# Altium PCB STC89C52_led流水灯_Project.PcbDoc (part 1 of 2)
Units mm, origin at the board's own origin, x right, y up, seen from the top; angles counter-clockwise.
Board outline 100 x 80 mm, 2 copper layers (Top Layer, Bottom Layer); 175 components, 183 nets, 540 pads, 112 vias.
Unrouted connection lines stored in the file: 28.
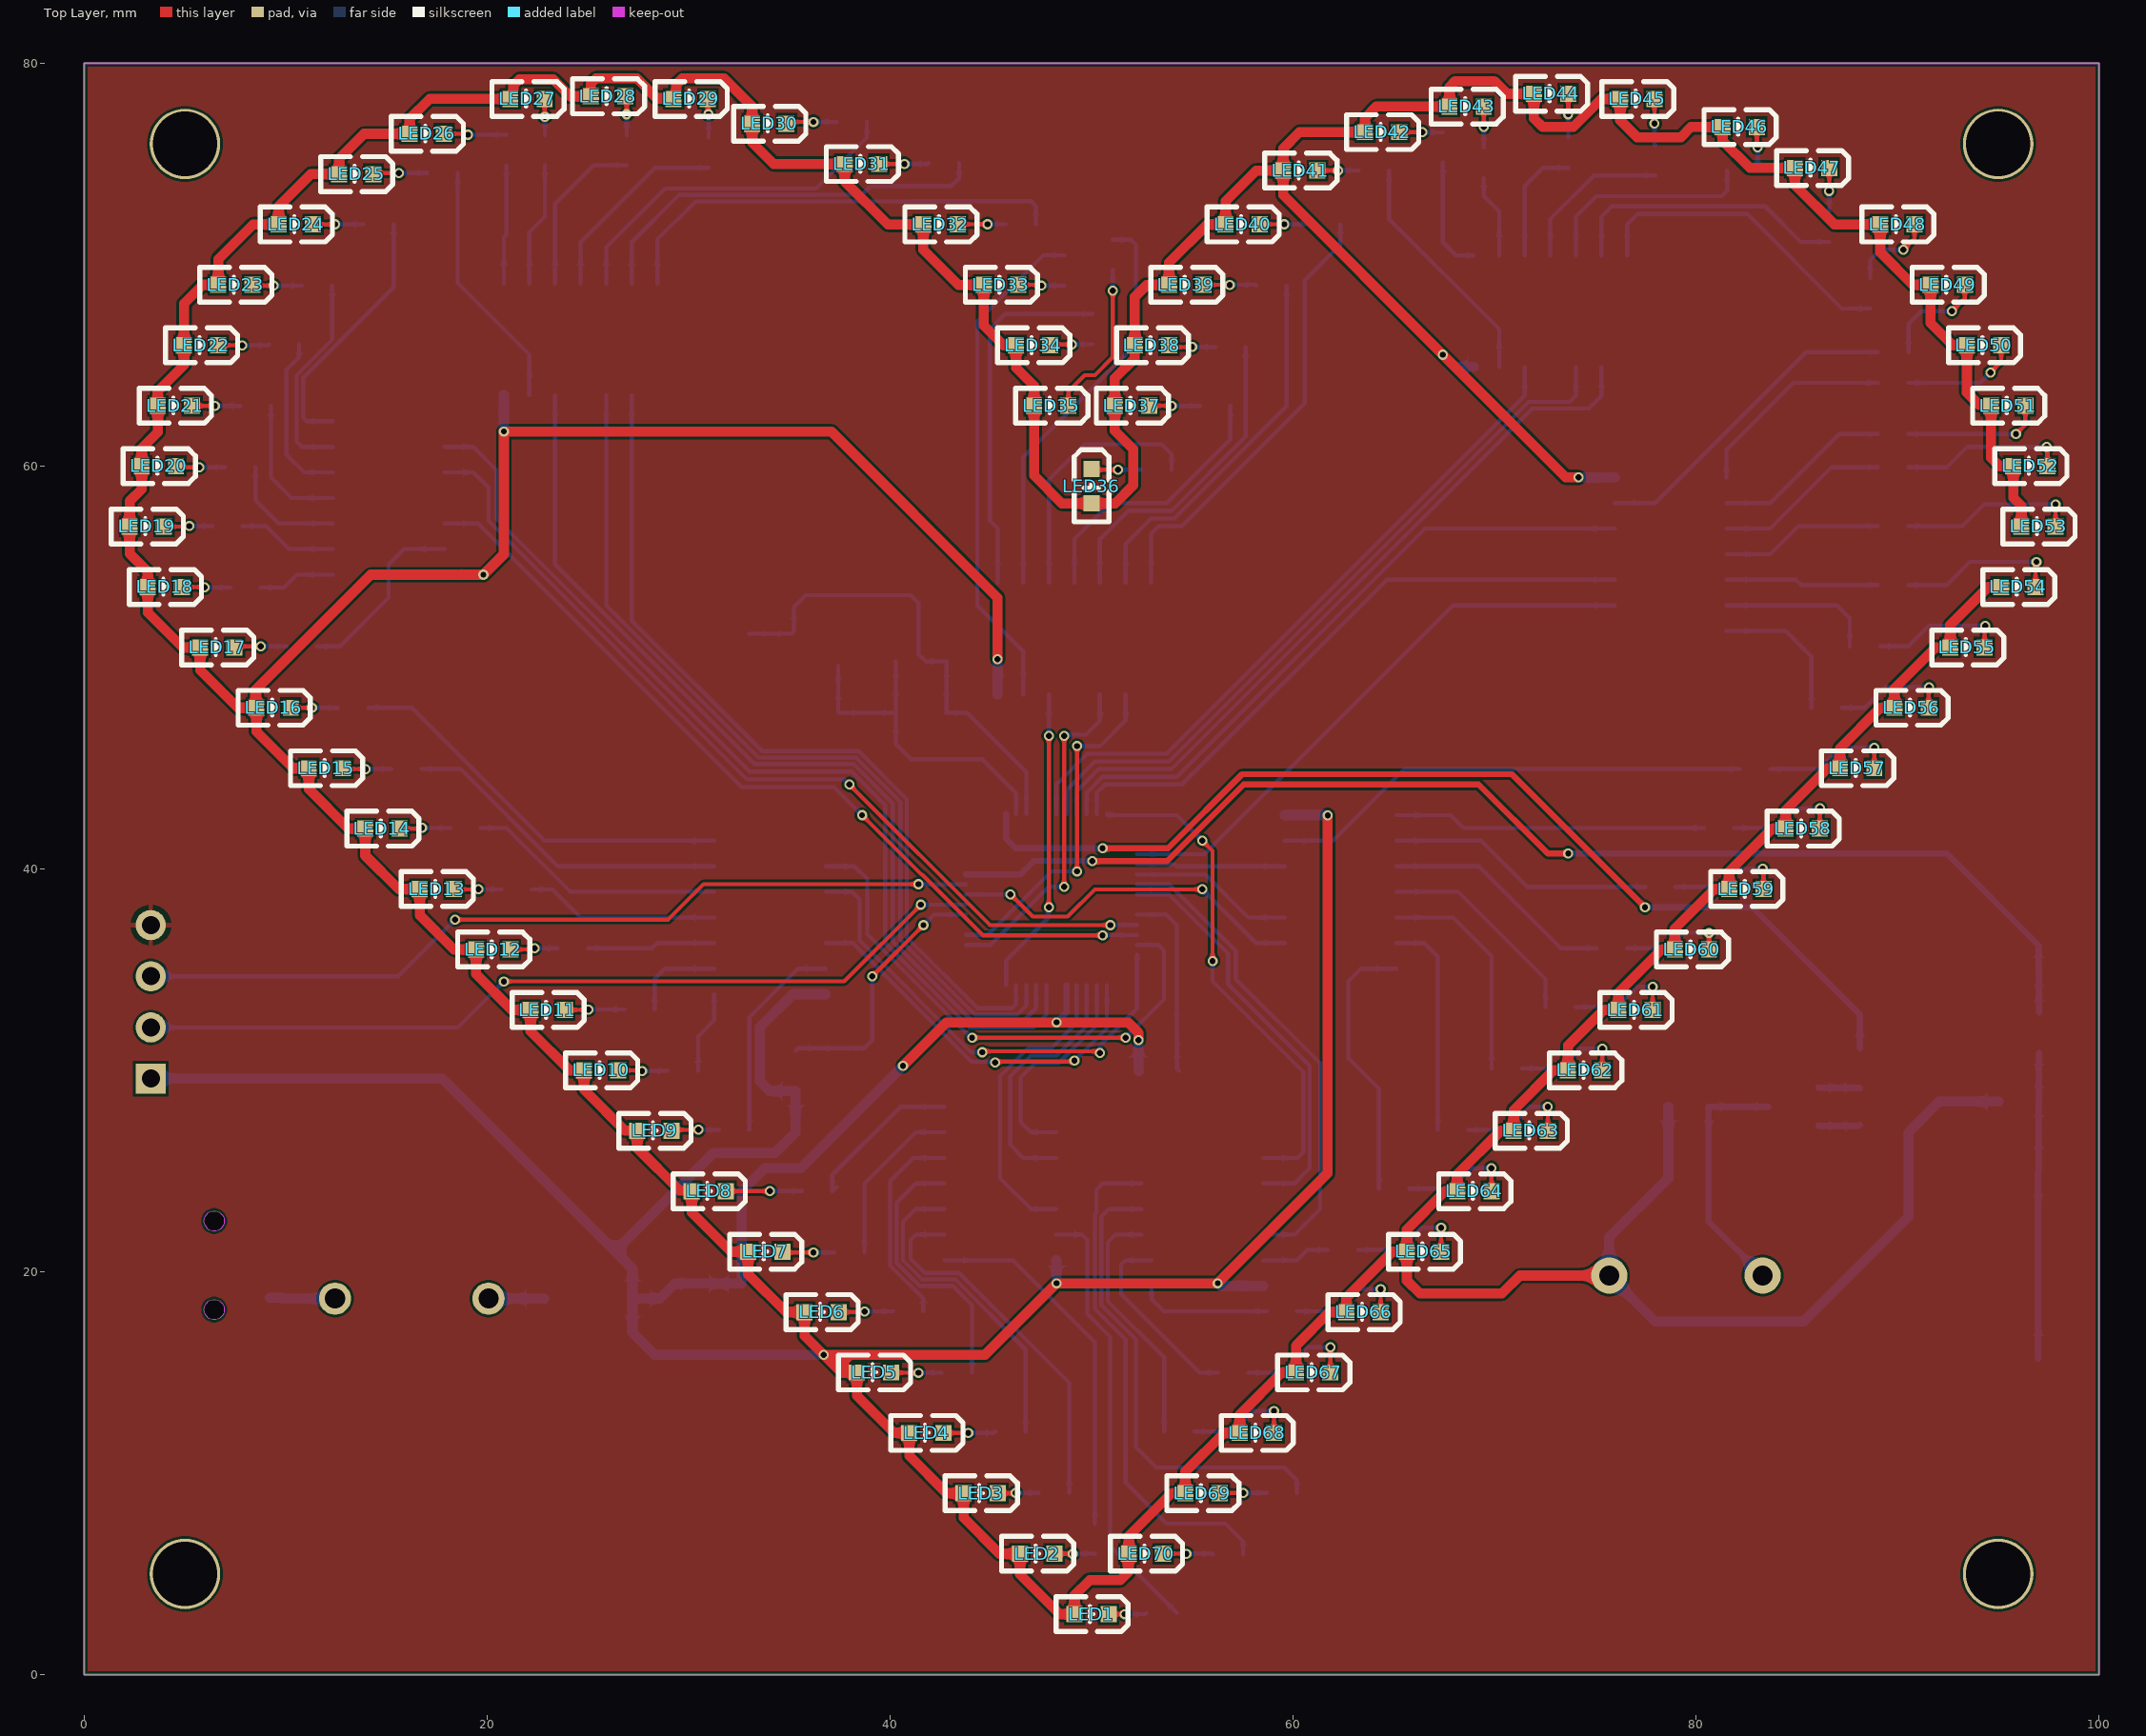
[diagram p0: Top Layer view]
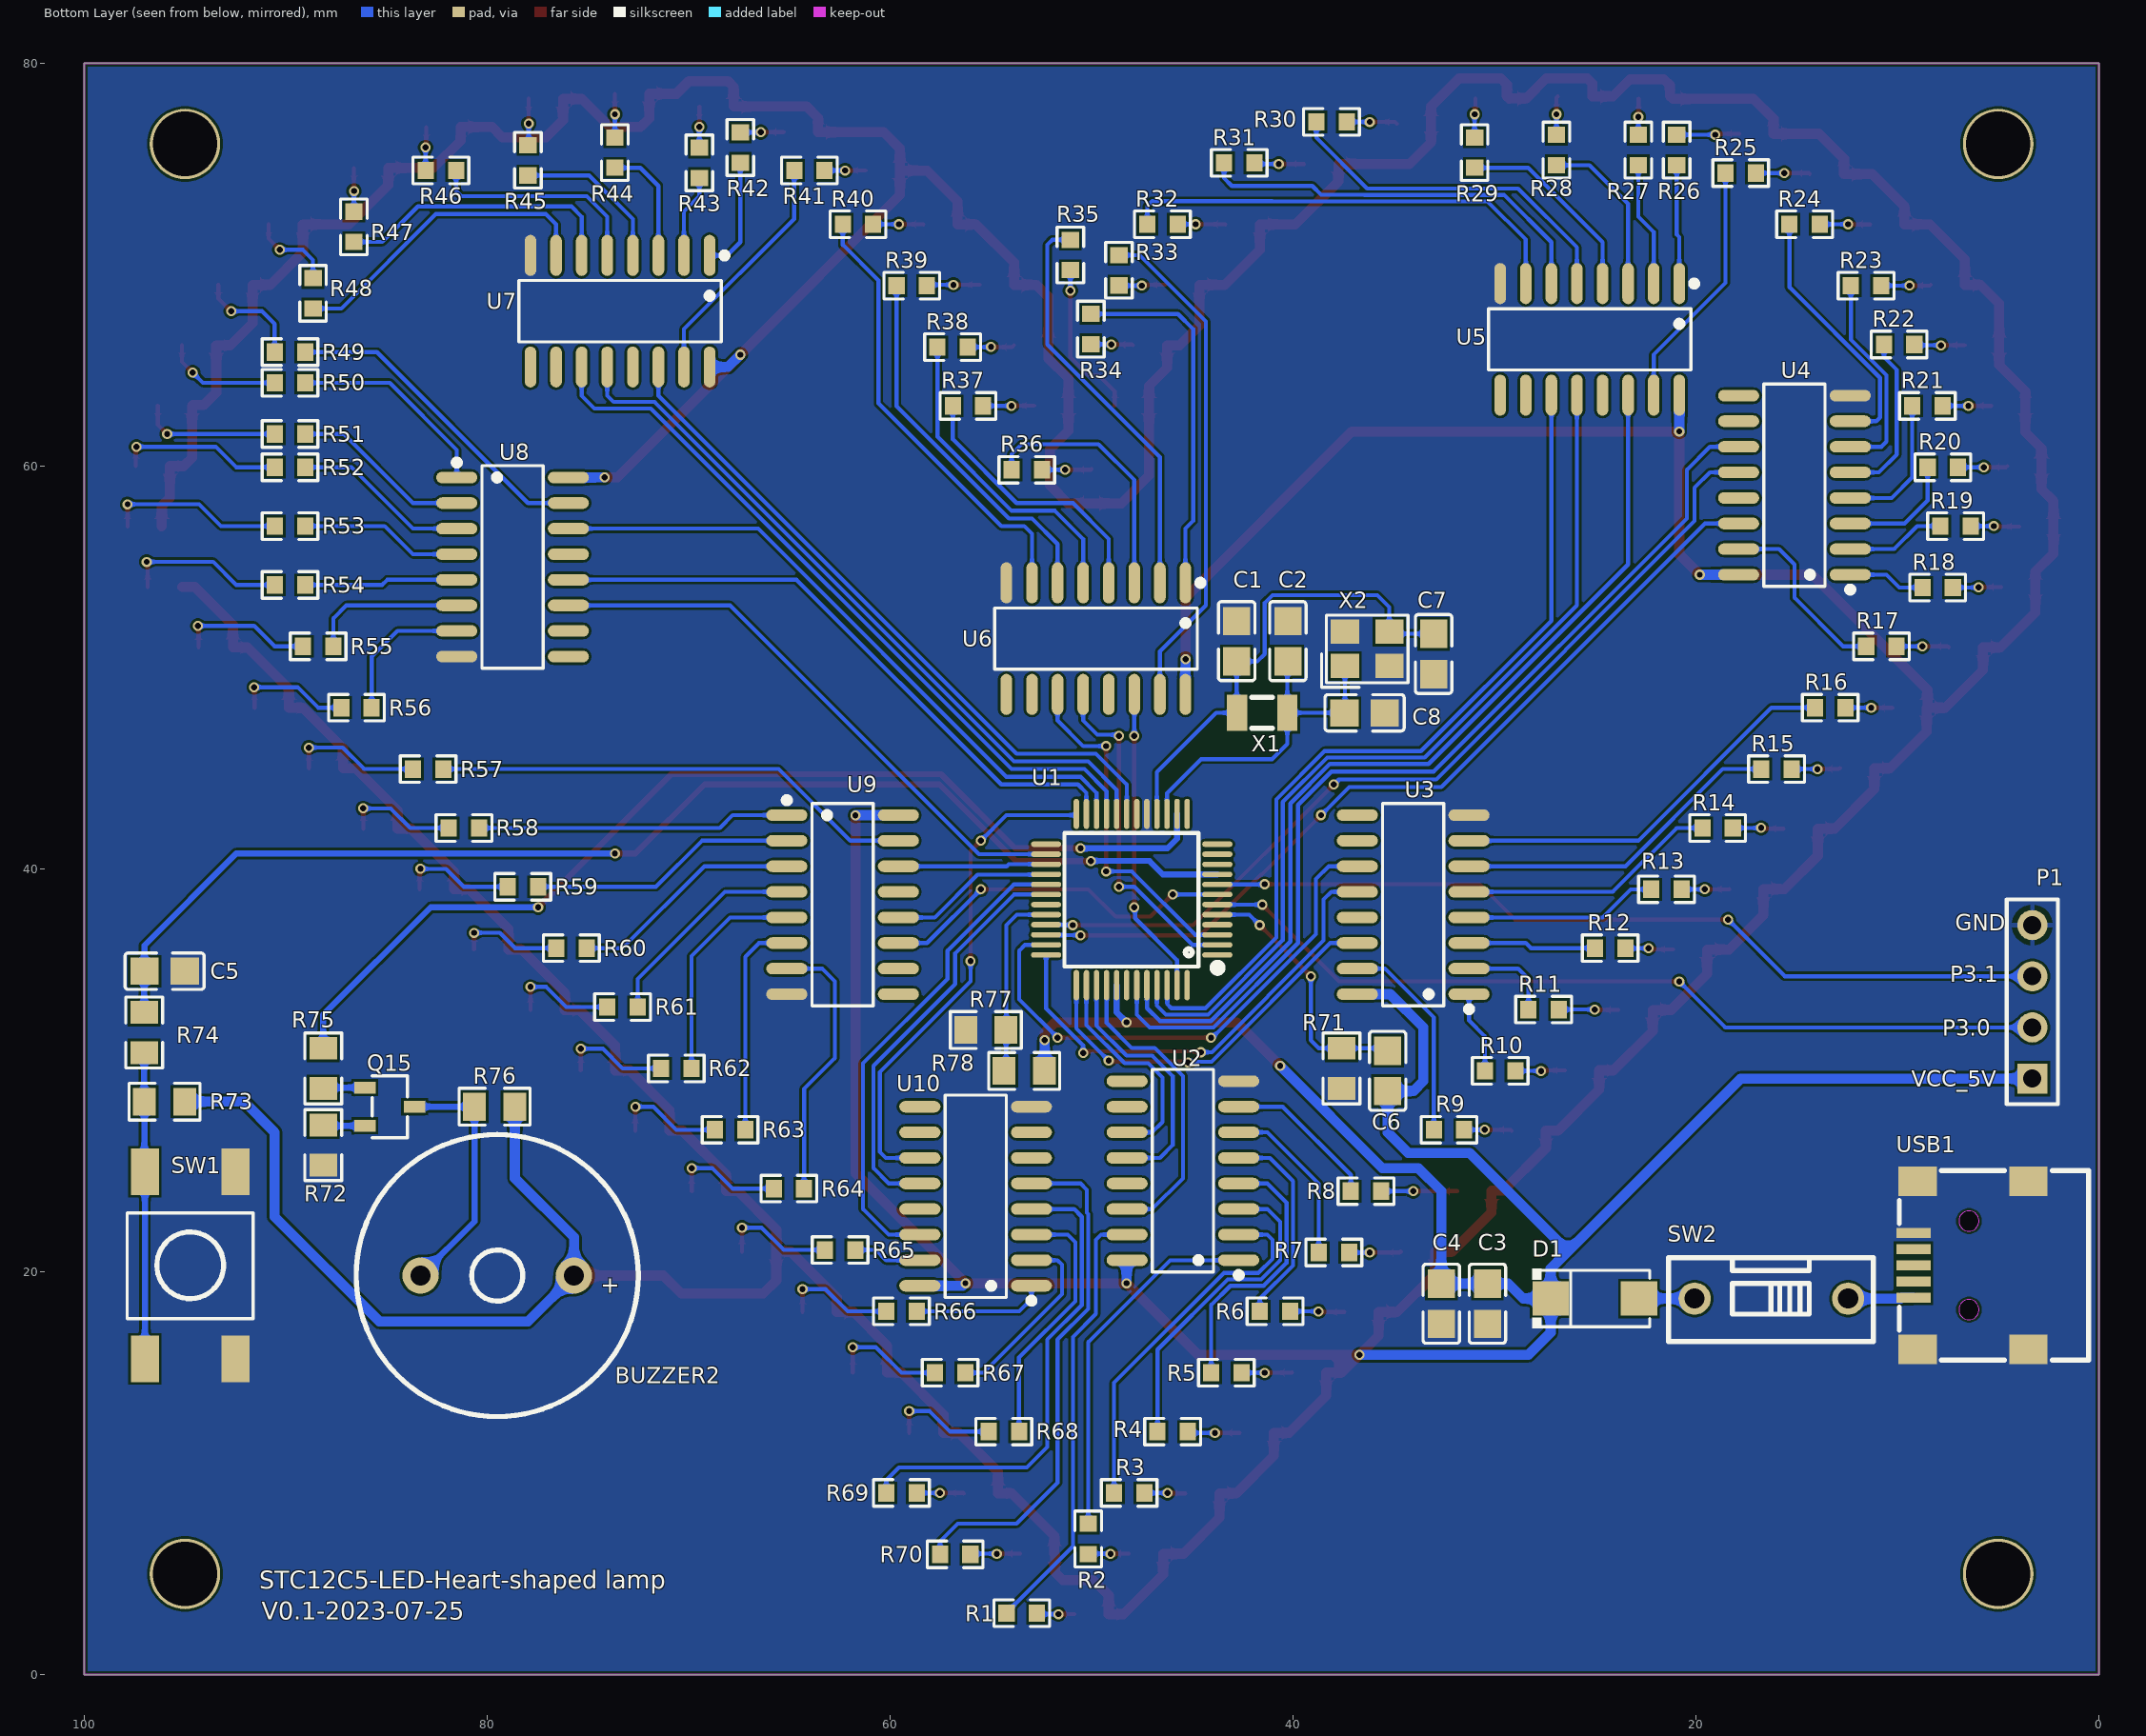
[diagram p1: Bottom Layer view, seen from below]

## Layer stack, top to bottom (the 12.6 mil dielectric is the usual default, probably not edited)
Top Solder: solder mask 0.0102, Solder Resist, Dk 3.5
Top Layer: signal copper 0.0356
Dielectric 1: dielectric 0.32, FR-4, Dk 4.8
Bottom Layer: signal copper 0.0356
Bottom Solder: solder mask 0.0102, Solder Resist, Dk 3.5

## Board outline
0,0 100,0 100,80 0,80

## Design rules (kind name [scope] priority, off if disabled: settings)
Clearance [All] p1: gap=0.12 ignorepadtopadclearanceinfootprint=FALSE
PolygonConnect [All] p1: thpad.connectstyle=Relief thpad.reliefconductorwidth=0.254 thpad.reliefentries=4 thpad.polygonreliefangle="90 Angle" thpad.airgapwidth=0.254 smdpad.connectstyle=Direct smdpad.reliefconductorwidth=0.254 smdpad.reliefentries=4 smdpad.polygonreliefangle="90 Angle" smdpad.airgapwidth=0.254 via.connectstyle=Direct via.reliefconductorwidth=0.254 via.reliefentries=4 via.polygonreliefangle="90 Angle" via.airgapwidth=0.254
RoutingVias [All] p1: holewidth=0.711 width=1.27 viastyle="Through Hole" minholewidth=0.3 minwidth=0.5 maxholewidth=0.711 maxwidth=1.27
SolderMaskExpansion [All] p1: expansion=0.102 istentingtop=FALSE
Width [All] p1: maxlimit=0.8 minlimit=0.16 preferedwidth=0.2
30 further rules are at their usual default settings.

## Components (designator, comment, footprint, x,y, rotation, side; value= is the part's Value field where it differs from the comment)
BUZZER2 "SFN-14045PA7.6" 插件,D=14mm 79.502,19.812 r0 bottom value=4000Hz
C1 "" C0805 42.799,51.308 r90 bottom value=22pF
C2 "" C0805 40.259,51.308 r90 bottom value=22pF
C3 "47uF" C0805 30.353,18.415 r90 bottom value=100uF
C4 "0.1uF" C0805 32.639,18.415 r90 bottom value=100uF
C5 "" C0805 96.012,34.925 r0 bottom value=0.1uF
C6 "" C0805 35.306,29.972 r270 bottom value=10uF
C7 "" C0805 33.02,50.673 r270 bottom value=22pF
C8 "" C0805 36.449,47.752 r180 bottom value=22pF
D1 "1N5819" SMA_L4.4-W2.6-LS5.0-RD 25.019,18.669 r180 bottom
LED1 "TLMG1100-GS08" LED0603 50,3 r180 top locked
LED2 "TLMG1100-GS08" LED0603 47.3,6 r180 top
LED3 "TLMG1100-GS08" LED0603 44.5,9 r180 top
LED4 "TLMG1100-GS08" LED0603 41.8,12 r180 top
LED5 "TLMG1100-GS08" LED0603 39.2,15 r180 top
LED6 "TLMG1100-GS08" LED0603 36.6,18 r180 top
LED7 "TLMG1100-GS08" LED0603 33.8,21 r180 top
LED8 "TLMG1100-GS08" LED0603 31,24 r180 top
LED9 "TLMG1100-GS08" LED0603 28.3,27 r180 top
LED10 "TLMG1100-GS08" LED0603 25.654,30 r180 top
LED11 "TLMG1100-GS08" LED0603 23,33 r180 top
LED12 "TLMG1100-GS08" LED0603 20.3,36 r180 top
LED13 "TLMG1100-GS08" LED0603 17.5,39 r180 top
LED14 "TLMG1100-GS08" LED0603 14.8,42 r180 top
LED15 "TLMG1100-GS08" LED0603 12,45 r180 top
LED16 "TLMG1100-GS08" LED0603 9.4,48 r180 top
LED17 "TLMG1100-GS08" LED0603 6.6,51 r180 top
LED18 "TLMG1100-GS08" LED0603 4,54 r180 top
LED19 "TLMG1100-GS08" LED0603 3.1,57 r180 top
LED20 "TLMG1100-GS08" LED0603 3.7,60 r180 top
LED21 "TLMG1100-GS08" LED0603 4.5,63 r180 top
LED22 "TLMG1100-GS08" LED0603 5.8,66 r180 top
LED23 "TLMG1100-GS08" LED0603 7.5,69 r180 top
LED24 "TLMG1100-GS08" LED0603 10.5,72 r180 top
LED25 "TLMG1100-GS08" LED0603 13.5,74.5 r180 top
LED26 "TLMG1100-GS08" LED0603 17,76.5 r180 top
LED27 "TLMG1100-GS08" LED0603 22,78.232 r180 top
LED28 "TLMG1100-GS08" LED0603 26,78.359 r180 top
LED29 "TLMG1100-GS08" LED0603 30.099,78.232 r180 top
LED30 "TLMG1100-GS08" LED0603 34,77 r180 top
LED31 "TLMG1100-GS08" LED0603 38.6,75 r180 top
LED32 "TLMG1100-GS08" LED0603 42.5,72 r180 top
LED33 "TLMG1100-GS08" LED0603 45.5,69 r180 top
LED34 "TLMG1100-GS08" LED0603 47.1,66 r180 top
LED35 "TLMG1100-GS08" LED0603 48,63 r180 top
LED36 "TLMG1100-GS08" LED0603 50,59 r270 top
LED37 "TLMG1100-GS08" LED0603 52,63 r180 top
LED38 "TLMG1100-GS08" LED0603 53,66 r180 top
LED39 "TLMG1100-GS08" LED0603 54.7,69 r180 top
LED40 "TLMG1100-GS08" LED0603 57.5,72 r180 top
LED41 "TLMG1100-GS08" LED0603 60.363,74.676 r180 top
LED42 "TLMG1100-GS08" LED0603 64.427,76.581 r180 top
LED43 "TLMG1100-GS08" LED0603 68.618,77.851 r180 top
LED44 "TLMG1100-GS08" LED0603 72.809,78.486 r180 top
LED45 "TLMG1100-GS08" LED0603 77.089,78.232 r180 top
LED46 "TLMG1100-GS08" LED0603 82.169,76.835 r180 top
LED47 "TLMG1100-GS08" LED0603 85.763,74.803 r180 top
LED48 "TLMG1100-GS08" LED0603 90,72 r180 top
LED49 "TLMG1100-GS08" LED0603 92.5,69 r180 top
LED50 "TLMG1100-GS08" LED0603 94.3,66 r180 top
LED51 "TLMG1100-GS08" LED0603 95.5,63 r180 top
LED52 "TLMG1100-GS08" LED0603 96.6,60 r180 top
LED53 "TLMG1100-GS08" LED0603 97,57 r180 top
LED54 "TLMG1100-GS08" LED0603 96,54 r180 top
LED55 "TLMG1100-GS08" LED0603 93.472,51 r180 top
LED56 "TLMG1100-GS08" LED0603 90.7,48 r180 top
LED57 "TLMG1100-GS08" LED0603 88,45 r180 top
LED58 "TLMG1100-GS08" LED0603 85.3,42 r180 top
LED59 "TLMG1100-GS08" LED0603 82.5,39 r180 top
LED60 "TLMG1100-GS08" LED0603 79.8,36 r180 top
LED61 "TLMG1100-GS08" LED0603 77,33 r180 top
LED62 "TLMG1100-GS08" LED0603 74.5,30 r180 top
LED63 "TLMG1100-GS08" LED0603 71.8,27 r180 top
LED64 "TLMG1100-GS08" LED0603 69,24 r180 top
LED65 "TLMG1100-GS08" LED0603 66.5,21 r180 top
LED66 "TLMG1100-GS08" LED0603 63.5,18 r180 top
LED67 "TLMG1100-GS08" LED0603 61,15 r180 top
LED68 "TLMG1100-GS08" LED0603 58.204,12 r180 top
LED69 "TLMG1100-GS08" LED0603 55.5,9 r180 top
LED70 "TLMG1100-GS08" LED0603 52.7,6 r180 top
P1 "2.54*4-P排针" HDR1X4 3.302,29.591 r90 bottom locked
Q15 "S8050" SOT-23 84.836,28.194 r0 bottom
R1 "" R0603 53.467,3.048 r180 bottom value=1k
R2 "" R0603 50.165,6.731 r270 bottom value=1k
R3 "" R0603 48.133,9.017 r180 bottom value=1k
R4 "" R0603 45.974,12.065 r180 bottom value=1k
R5 "" R0603 43.307,14.986 r180 bottom value=1k
R6 "" R0603 40.894,18.034 r180 bottom value=1k
R7 "" R0603 37.973,20.955 r180 bottom value=1k
R8 "" R0603 36.376,24.003 r180 bottom value=1k
R9 "" R0603 32.258,27.051 r180 bottom value=1k
R10 "" R0603 29.718,29.972 r180 bottom value=1k
R11 "" R0603 27.559,33.02 r180 bottom value=1k
R12 "" R0603 24.257,36.068 r180 bottom value=1k
R13 "" R0603 21.463,38.989 r180 bottom value=1k
R14 "" R0603 18.923,42.037 r180 bottom value=1k
R15 "" R0603 16.002,44.958 r180 bottom value=1k
R16 "" R0603 13.335,48.006 r180 bottom value=1k
R17 "" R0603 10.795,51.054 r180 bottom value=1k
R18 "" R0603 8.001,53.975 r180 bottom value=1k
R19 "" R0603 7.112,57.023 r180 bottom value=1k
R20 "" R0603 7.747,59.944 r180 bottom value=1k
R21 "" R0603 8.509,62.992 r180 bottom value=1k
R22 "" R0603 9.915,66.04 r180 bottom value=1k
R23 "" R0603 11.557,68.961 r180 bottom value=1k
R24 "" R0603 14.605,72.009 r180 bottom value=1k
R25 "" R0603 17.78,74.549 r180 bottom value=1k
R26 "" R0603 20.955,75.692 r90 bottom value=1k
R27 "" R0603 22.86,75.692 r90 bottom value=1k
R28 "" R0603 26.924,75.692 r90 bottom value=1k
R29 "" R0603 30.988,75.565 r90 bottom value=1k
R30 "" R0603 38.091,77.089 r180 bottom value=1k
R31 "" R0603 42.672,75.057 r180 bottom value=1k
R32 "" R0603 46.482,72.009 r180 bottom value=1k
R33 "" R0603 48.641,69.723 r270 bottom value=1k
R34 "" R0603 50.038,66.802 r270 bottom value=1k
R35 "" R0603 51.054,70.485 r270 bottom value=1k
R36 "" R0603 53.213,59.817 r180 bottom value=1k
R37 "" R0603 56.134,62.992 r180 bottom value=1k
R38 "" R0603 56.896,65.913 r180 bottom value=1k
R39 "" R0603 58.928,68.961 r180 bottom value=1k
R40 "" R0603 61.595,72.009 r180 bottom value=1k
R41 "" R0603 64.008,74.676 r180 bottom value=1k
R42 "" R0603 67.437,75.819 r90 bottom value=1k
R43 "" R0603 69.469,75.057 r90 bottom value=1k
R44 "" R0603 73.66,75.565 r90 bottom value=1k
R45 "" R0603 77.978,75.184 r90 bottom value=1k
R46 "" R0603 82.296,74.676 r0 bottom value=1k
R47 "" R0603 86.614,71.882 r90 bottom value=1k
R48 "" R0603 88.646,68.58 r90 bottom value=1k
R49 "" R0603 89.789,65.659 r0 bottom value=1k
R50 "" R0603 89.789,64.135 r0 bottom value=1k
R51 "" R0603 89.789,61.595 r0 bottom value=1k
R52 "" R0603 89.789,59.944 r0 bottom value=1k
R53 "" R0603 89.789,57.023 r0 bottom value=1k
R54 "" R0603 89.789,54.102 r0 bottom value=1k
R55 "" R0603 88.392,51.054 r0 bottom value=1k
R56 "" R0603 86.487,48.006 r0 bottom value=1k
R57 "" R0603 82.931,44.958 r0 bottom value=1k
R58 "" R0603 81.153,42.037 r0 bottom value=1k
R59 "" R0603 78.232,39.116 r0 bottom value=1k
R60 "" R0603 75.819,36.068 r0 bottom value=1k
R61 "" R0603 73.279,33.147 r0 bottom value=1k
R62 "" R0603 70.612,30.099 r0 bottom value=1k
R63 "" R0603 67.945,27.051 r0 bottom value=1k
R64 "" R0603 65.024,24.13 r0 bottom value=1k
R65 "" R0603 62.484,21.082 r0 bottom value=1k
R66 "" R0603 59.436,18.034 r0 bottom value=1k
R67 "" R0603 57.023,14.986 r0 bottom value=1k
R68 "" R0603 54.356,12.065 r0 bottom value=1k
R69 "" R0603 59.436,9.017 r180 bottom value=1k
R70 "" R0603 56.769,5.969 r180 bottom value=1k
R71 "" R0805 37.592,30.099 r90 bottom value=10k
R72 "" R0805 88.138,26.289 r90 bottom value=0
R73 "" R0805 96.012,28.448 r180 bottom value=2M
R74 "" R0805 97.028,31.877 r90 bottom value=4.7k
R75 "" R0805 88.138,30.099 r90 bottom value=100
R76 "" R0805 79.629,28.194 r180 bottom value=1k
R77 "10K" R0805 55.245,32.004 r180 bottom
R78 "20K" R0805 53.34,29.972 r180 bottom
SW1 "1TS005F-2500-5001" KEY-SMD_4P-L6.0-W6.0 94.742,20.32 r180 bottom
SW2 "DSWB01LHGET" SW-TH_DSWB01LHGET 16.256,18.669 r270 bottom
U1 "STC12C5A60S2-35I-LQFP48" LQFP-48_L7.0-W7.0 48.006,38.481 r90 bottom
U2 "74HC595D" SOP-16 45.466,25.019 r90 bottom
U3 "74HC595D." SOP-16 34.036,38.227 r90 bottom
U4 "74HC595D." SOP-16 15.113,59.055 r90 bottom
U5 "74HC595D." SOP-16 25.273,66.294 r0 bottom
U6 "74HC595D." SOP-16 49.784,51.435 r0 bottom
U7 "74HC595D." SOP-16 73.406,67.691 r0 bottom
U8 "74HC595D." SOP-16 78.74,54.991 r270 bottom
U9 "74HC595D." SOP-16 62.357,38.227 r270 bottom
U10 "74HC595D." SOP-16 55.753,23.749 r90 bottom
USB1 "UX-144S-ACP5" MINI-USB-SMD_UX-144S-ACP5 6.35,20.32 r90 bottom
X1 "Q13FC1350000400" SMD3215-2P 41.529,47.752 r0 bottom value=-
X2 "TAXM12M4RFBCCT2T" SMD3225-4P 36.322,50.927 r180 bottom value=12MHz

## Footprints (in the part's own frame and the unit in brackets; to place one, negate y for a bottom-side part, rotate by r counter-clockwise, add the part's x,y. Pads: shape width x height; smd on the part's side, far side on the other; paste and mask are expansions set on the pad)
C0805 [mm]
  rect 1.41x1.35 smd mask+0.051: 1(-1,0) 2(1,0)
  silkscreen extent -1.96,-0.9 1.96,0.9
HDR1X4 [mm] "Connector; Header; 4 Position"
  rect 1.5x1.5 hole 0.9: 1(0,0)
  round 1.5 hole 0.9: 2(2.54,0) 3(5.08,0) 4(7.62,0)
  silkscreen extent -1.27,-1.27 8.89,1.27
KEY-SMD_4P-L6.0-W6.0 [mm]
  rect 1.4x2.3 smd: 1(-2.25,-4.643) 2(-2.25,4.643) 3(2.25,4.643) 4(2.25,-4.643)
  silkscreen extent -3.13,-2.65 3.13,2.6
LED0603 [mm]
  rect 0.8x0.8 smd paste+0 mask+0.051: 1(0.851,0) 2(-0.851,0)
  silkscreen extent -1.82,-0.86 1.77,0.86
LQFP-48_L7.0-W7.0 [mm]
  oval 0.27x1.5 smd paste+0 mask+0.05: 1(-2.75,-4.25) 2(-2.25,-4.25) 3(-1.75,-4.25) 4(-1.25,-4.25) 5(-0.75,-4.25) 6(-0.25,-4.25) 7(0.25,-4.25) 8(0.75,-4.25) 9(1.25,-4.25) 10(1.75,-4.25) 11(2.25,-4.25) 12(2.75,-4.25) 25(2.75,4.25) 26(2.25,4.25) 27(1.75,4.25) 28(1.25,4.25) 29(0.75,4.25) 30(0.25,4.25) 31(-0.25,4.25) 32(-0.75,4.25) 33(-1.25,4.25) 34(-1.75,4.25) 35(-2.25,4.25) 36(-2.75,4.25)
  oval 1.5x0.27 smd paste+0 mask+0.05: 13(4.25,-2.75) 14(4.25,-2.25) 15(4.25,-1.75) 16(4.25,-1.25) 17(4.25,-0.75) 18(4.25,-0.25) 19(4.25,0.25) 20(4.25,0.75) 21(4.25,1.25) 22(4.25,1.75) 23(4.25,2.25) 24(4.25,2.75) 37(-4.25,2.75) 38(-4.25,2.25) 39(-4.25,1.75) 40(-4.25,1.25) 41(-4.25,0.75) 42(-4.25,0.25) 43(-4.25,-0.25) 44(-4.25,-0.75) 45(-4.25,-1.25) 46(-4.25,-1.75) 47(-4.25,-2.25) 48(-4.25,-2.75)
  silkscreen extent -3.59,-4.46 3.3,3.34
MINI-USB-SMD_UX-144S-ACP5 [mm]
  rect 0.5x1.7 smd: 1(-1.6,2.85) 2(-0.8,2.85) 3(0,2.85) 4(0.8,2.85) 5(1.6,2.85)
  rect 1.45x1.9 smd: 6(-4.175,2.65) 7(-4.175,-2.85) 8(4.175,-2.85) 9(4.175,2.65)
  Keep-Out Layer board cut-out: -1.7,0.1 -1.749,0.317 -1.888,0.491 -2.089,0.587 -2.311,0.587 -2.512,0.491 -2.65,0.317 -2.7,0.1 -2.7,0.1 -2.65,-0.117 -2.512,-0.291 -2.311,-0.388 -2.089,-0.388 -1.888,-0.291 -1.749,-0.117 -1.7,0.1
  Keep-Out Layer board cut-out: 2.7,0.1 2.651,0.317 2.512,0.491 2.311,0.587 2.089,0.587 1.888,0.491 1.75,0.317 1.7,0.1 1.7,0.1 1.75,-0.117 1.888,-0.291 2.089,-0.388 2.311,-0.388 2.512,-0.291 2.651,-0.117 2.7,0.1
  silkscreen extent -4.7,-5.84 4.7,3.56
R0603 [mm]
  rect 0.806x0.864 smd mask+0.051: 1(-0.753,0) 2(0.753,0)
  silkscreen extent -1.39,-0.66 1.39,0.66
R0805 [mm]
  rect 1.133x1.377 smd mask+0.051: 1(-1,0) 2(1,0)
  silkscreen extent -1.76,-0.92 1.76,0.92
SMA_L4.4-W2.6-LS5.0-RD [mm]
  rect 1.8x1.7 smd: 1(-2.192,0) 2(2.192,0)
  silkscreen extent -3.11,-1.48 2.73,1.48
SMD3215-2P [mm] "FC-135晶振"
  rect 1x1.8 smd: 1(-1.25,0) 2(1.25,0)
  silkscreen extent -0.51,-0.76 0.51,0.76
SMD3225-4P [mm]
  rect 1.4x1.2 smd: 1(-1.1,-0.85) 2(1.1,-0.85) 3(1.1,0.85) 4(-1.1,0.85)
  silkscreen extent -2.26,-1.91 2.03,1.68
SOP-16 [mm]
  oval 0.574x2.038 smd: 1(-4.445,-2.769) 2(-3.175,-2.769) 3(-1.905,-2.769) 4(-0.635,-2.769) 5(0.635,-2.769) 6(1.905,-2.769) 7(3.175,-2.769) 8(4.445,-2.769) 9(4.445,2.769) 10(3.175,2.769) 11(1.905,2.769) 12(0.635,2.769) 13(-0.635,2.769) 14(-1.905,2.769) 15(-3.175,2.769) 16(-4.445,2.769)
  silkscreen extent -5.33,-2.92 5.03,1.52
SOT-23 [mm]
  rect 1.07x0.6 smd paste+0 mask+0.051: 1(1.235,-0.95) 2(1.235,0.95) 3(-1.235,0)
  silkscreen extent -0.88,-1.54 0.88,1.54
SW-TH_DSWB01LHGET [mm] "插件"
  round 1.6 hole 1: 1(0,3.81) 2(0,-3.81)
  silkscreen extent -2.02,-5.11 2.13,5.05
插件,D=14mm [mm] "蜂鸣器"
  round 1.8 hole 1: 1(-3.81,0) 2(3.81,0)
  silkscreen extent -7,-7 7,7

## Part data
BUZZER2: library part GPC12075YB-5V, "品牌：S&S(海旭)", JLCPCB Part Class="Extended Part", Manufacturer=INGHAi(赢海), Rated Voltage=5V
C1 C2 C3 C4 C5 C6 C7 C8: library part C?, JLCPCB Part Class="Extended Part", LCSC Part Name="100uF ±20% 6.3V", Manufacturer=muRata(村田), Manufacturer Part=GRM21BR60J107ME15L, Temperature Coefficient=X5R, Tolerance=±20%, Voltage Rated=6.3V
D1: library part 1N5819_C437199, "品牌：KEXIN(科信)", Average Rectified Current (Io)=1A, Forward Voltage (Vf@If)=500mV@1A, JLCPCB Part Class="Extended Part", LCSC Part Name="40V 1A 500mV@1A", Manufacturer=KEXIN(科信), Reverse Voltage (Vr)=40V
LED1 LED2 LED3 LED4 LED5 LED6 LED7 LED8 LED9 LED10 LED11 LED12 LED13 LED14 LED15 LED16 LED17 LED18 LED19 LED20 LED21 LED22 LED23 LED24 LED25 LED26 LED27 LED28 LED29 LED30 LED31 LED32 LED33 LED34 LED35 LED36 LED37 LED38 LED39 LED40 LED41 LED42 LED43 LED44 LED45 LED46 LED47 LED48 LED49 LED50 LED51 LED52 LED53 LED54 LED55 LED56 LED57 LED58 LED59 LED60 LED61 LED62 LED63 LED64 LED65 LED66 LED67 LED68 LED69 LED70: "LED?", Correlated Color Temperature - CCT(K)=-, Illumination Color=普绿/黄绿, JLCPCB Part Class="Extended Part", LCSC Part Name="普绿/黄绿 0603", Manufacturer=VISHAY(威世)
P1: library part "Header 4", "生产不焊接"
Q15: Collector Current (Ic)=500mA, Collector Cut-Off Current (Icbo)=100nA, Collector-Emitter Breakdown Voltage (Vceo)=25V, Collector-Emitter Saturation Voltage (VCE(sat)@Ic,Ib)=600mV@500mA,50mA, JLCPCB Part Class="Extended Part", LCSC Part Name="NPN 25V 500mA", Manufacturer=Hottech(合科泰), Operating Temperature=+150℃@(Tj), Power Dissipation (Pd)=300mW, Transition Frequency (fT)=150MHz
R1 R2 R3 R4 R5 R6 R7 R8 R9 R10 R11 R12 R13 R14 R15 R16 R17 R18 R19 R20 R21 R22 R23 R24 R25 R26 R27 R28 R29 R30 R31 R32 R33 R34 R35 R36 R37 R38 R39 R40 R41 R42 R43 R44 R45 R46 R47 R48 R49 R50 R51 R52 R53 R54 R55 R56 R57 R58 R59 R60 R61 R62 R63 R64 R65 R66 R67 R68 R69 R70 R71 R72 R73 R74 R75 R76: library part ERJPB6B1001V, JLCPCB Part Class="Extended Part", LCSC Part Name="1KΩ(1001) ±0.1%", Manufacturer=PANASONIC(松下)
R77 R78: library part ERJPB6B1001V, "R", JLCPCB Part Class="Extended Part", LCSC Part Name="1KΩ(1001) ±0.1%", Manufacturer=PANASONIC(松下)
SW1: "品牌： HYP(鸿源精密)", Actuator/Cap Color=黑色, Contact Current=50mA, Insulation Resistance=100MΩ, JLCPCB Part Class="Extended Part", LCSC Part Name="6*6*5mm 立贴 轻触开关", Manufacturer=HYP(鸿源精密), Operating Force=250gf@±50gf, Operating Temperature=-40℃~+90℃, Power Rating=0.6W, Voltage Rating (DC)=12V
SW2: Color=红色, JLCPCB Part Class="Extended Part", LCSC Part Name=红色宽体1位顶拨插件, Manufacturer=YE, Operating Life=-
U1: JLCPCB Part Class="Extended Part", LCSC Part Name="51系列 35MHz", Low-Voltage Detect=有, Manufacturer=STC(宏晶), Operating Temperature Range=-40℃~+85℃, Operating Voltage Range=4V~5.5V
U2: library part 74HC595D., "品牌： JSMSEMI(杰盛微)"
U3 U4 U5 U6 U7 U8 U9 U10: "品牌： JSMSEMI(杰盛微)"
USB1: "品牌： XUNPU(讯普)", Current Rating - Power (Max)=1.5A, JLCPCB Part Class="Extended Part", LCSC Part Name="Mini-B 母座 卧贴", Manufacturer=XUNPU(讯普), Operating Temperature Range=-20℃~+70℃, Welding Temperature (Max)=260℃
X1: library part X？, "品牌： EPSON(爱普生)", JLCPCB Part Class="Extended Part", LCSC Part Name="32.768KHz 12.5PF 20ppm", Load Capacitance=-, Manufacturer=KDS(大真空), Manufacturer Part="DST310S 32.768KHz"
X2: "品牌： TAE(雅晶鑫)", Equivalent Series Resistance (ESR)=80Ω, Frequency Stability=±50ppm, Frequency Tolerance=±10ppm, JLCPCB Part Class="Extended Part", LCSC Part Name="12MHz ±10ppm 12pF", Load Capacitance=12pF, Manufacturer=TAE(雅晶鑫), Operating Temperature=-

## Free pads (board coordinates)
  round 3.5 hole 3.2 mask+0.102: 1(5,5) 2(95,5) 3(95,76) 4(5,76)

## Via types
v1: diameter 0.5, hole 0.3, Top Layer to Bottom Layer, tented both sides, 112 vias

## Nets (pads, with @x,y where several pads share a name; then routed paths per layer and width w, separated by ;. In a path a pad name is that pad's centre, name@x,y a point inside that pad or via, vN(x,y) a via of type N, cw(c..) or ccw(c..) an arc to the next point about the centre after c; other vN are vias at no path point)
EX_LVD: R77.2 R78.1 U1.32 | length 9.5
  Bottom Layer w0.2: U1.32@52.256,37.731 53.709,37.731 54.229,37.211 54.229,32.02 R77.2@54.245,32.004 54.245,30.067 R78.1@54.34,29.972
GND: C1.2 C2.2 C3.1 C4.1 C5.1 C7.2 C8.2 P1.4 R71.1 R72.1 R77.1 SW1.3 SW1.4 U1.17 U2.8 U3.8 U4.8 U5.8 U6.8 U7.8 U8.8 U9.8 U10.8 USB1.5 USB1.6 USB1.7 USB1.8 USB1.9 X2.2 X2.4
LED1: R1.1 U2.15 | length 22
  Bottom Layer w0.2: U2.15@48.235,21.844 49.53,21.844 49.784,21.59 49.784,17.907 50.927,16.764 50.927,6.37 54.22,3.077 R1.1@54.22,3.048
LED2: R2.1 U2.1 | length 18.2
  Bottom Layer w0.2: U2.1@42.697,20.574 46.101,20.574 50.165,16.51 R2.1@50.165,7.484
LED3: R3.1 U2.2 | length 18.6
  Bottom Layer w0.2: U2.2@42.697,21.844 41.275,21.844 41.021,21.59 41.021,20.646 41.723,19.944 43.429,19.944 48.886,14.487 R3.1@48.886,9.017
LED4: R4.1 U2.3 | length 16.2
  Bottom Layer w0.2: U2.3@42.697,23.114 41.275,23.114 40.64,22.479 40.64,20.574 41.59,19.624 43.241,19.624 46.727,16.138 R4.1@46.727,12.065
LED5: R5.1 U2.4 | length 13.7
  Bottom Layer w0.2: U2.4@42.697,24.384 41.275,24.384 40.32,23.429 40.32,20.441 41.457,19.304 43.108,19.304 44.06,18.352 R5.1@44.06,14.986
LED6: R6.1 U2.5 | length 10.3
  Bottom Layer w0.2: R6.1@41.647,18.034 41.647,18.662 40,20.309 40,24.506 41.148,25.654 U2.5@42.697,25.654
LED7: R7.1 U2.6 | length 8.4
  Bottom Layer w0.2: R7.1@38.726,20.955 38.726,24.375 41.275,26.924 U2.6@42.697,26.924
LED8: R8.1 U2.7 | length 8.1
  Bottom Layer w0.2: R8.1@37.338,24.211 R8.1@37.13,24.003 37.13,24.811 40.513,28.194 U2.7@42.697,28.194
LED9: R9.1 U3.15 | length 10.4
  Bottom Layer w0.2: R9.1@33.011,27.051 33.011,32.63 35.433,35.052 U3.15@36.805,35.052
LED10: R10.1 U3.1 | length 4.1
  Bottom Layer w0.2: R10.1@30.471,29.972 30.471,31.686 31.267,32.481 U3.1@31.267,33.782
LED11: R11.1 U3.2 | length 4.7
  Bottom Layer w0.2: R11.1@28.312,33.02 28.312,34.535 28.829,35.052 U3.2@31.267,35.052
LED12: R12.1 U3.3 | length 6.4
  Bottom Layer w0.2: R12.1@25.01,36.068 28.194,36.068 28.448,36.322 U3.3@31.267,36.322
LED13: R13.1 U3.4 | length 9.6
  Bottom Layer w0.2: R13.1@22.216,38.989 23.241,38.989 24.638,37.592 U3.4@31.267,37.592
LED14: R14.1 U3.5 | length 12.9
  Bottom Layer w0.2: R14.1@19.676,42.037 20.955,42.037 24.13,38.862 U3.5@31.267,38.862
LED15: R15.1 U3.6 | length 16.5
  Bottom Layer w0.2: R15.1@16.755,44.958 18.669,44.958 23.495,40.132 U3.6@31.267,40.132
LED16: R16.1 U3.7 | length 19.9
  Bottom Layer w0.2: R16.1@14.088,48.006 16.256,48.006 22.86,41.402 U3.7@31.267,41.402
LED17: R17.1 U4.15 | length 9.3
  Bottom Layer w0.2: R17.1@11.548,51.054 12.7,51.054 15.113,53.467 15.113,55.118 15.875,55.88 U4.15@17.882,55.88
LED18: R18.1 U4.1 | length 3.9
  Bottom Layer w0.2: R18.1@8.754,53.975 9.906,53.975 10.541,54.61 U4.1@12.344,54.61
LED19: R19.1 U4.2 | length 5
  Bottom Layer w0.2: R19.1@7.865,57.023 9.017,57.023 10.16,55.88 U4.2@12.344,55.88
LED20: R20.1 U4.3 | length 6
  Bottom Layer w0.2: R20.1@8.5,59.944 8.5,58.302 9.652,57.15 U4.3@12.344,57.15
LED21: R21.1 U4.4 | length 7.1
  Bottom Layer w0.2: R21.1@9.262,62.992 9.262,59.445 10.287,58.42 U4.4@12.344,58.42
LED22: R22.1 U4.5 | length 8.4
  Bottom Layer w0.2: R22.1@10.668,66.04 10.668,65.405 10.033,64.77 10.033,60.579 10.922,59.69 U4.5@12.344,59.69
LED23: R23.1 U4.6 | length 10.4
  Bottom Layer w0.2: R23.1@12.31,68.961 12.31,66.285 10.541,64.516 10.541,61.214 10.795,60.96 U4.6@12.344,60.96
LED24: R24.1 U4.7 | length 13
  Bottom Layer w0.2: U4.7@12.344,62.23 11.049,62.23 10.861,62.418 10.861,64.383 15.358,68.881 R24.1@15.358,72.009
LED25: R25.1 U5.15 | length 12.5
  Bottom Layer w0.2: R25.1@18.533,74.549 18.533,69.097 22.098,65.532 U5.15@22.098,63.525
LED26: R26.1 U5.1 | length 5.9
  Bottom Layer w0.2: U5.1@20.828,69.063 20.828,71.374 20.955,71.501 R26.1@20.955,74.939
LED27: R27.1 U5.2 | length 6.2
  Bottom Layer w0.2: U5.2@22.098,69.063 22.098,71.628 22.86,72.39 R27.1@22.86,74.939
LED28: R28.1 U5.3 | length 8.3
  Bottom Layer w0.2: U5.3@23.368,69.063 23.368,73.025 25.282,74.939 R28.1@26.924,74.939
LED29: R29.1 U5.4 | length 9.9
  Bottom Layer w0.2: U5.4@24.638,69.063 24.638,71.12 28.33,74.812 R29.1@30.988,74.812
LED30: R30.1 U5.5 | length 17.8
  Bottom Layer w0.2: U5.5@25.908,69.063 25.908,70.866 28.829,73.787 36.322,73.787 38.845,76.31 R30.1@38.845,77.089
LED31: R31.1 U5.6 | length 20.4
  Bottom Layer w0.2: U5.6@27.178,69.063 27.178,71.12 29.525,73.467 36.455,73.467 36.46,73.472 38.602,73.472 39.044,73.914 43.036,73.914 43.425,74.304 R31.1@43.425,75.057
LED32: R32.1 U5.7 | length 22.8
  Bottom Layer w0.2: U5.7@28.448,69.063 28.448,71.247 30.348,73.147 41.019,73.147 41.023,73.152 46.99,73.152 47.235,72.907 R32.1@47.235,72.009
LED33: R33.1 U6.15 | length 25.1
  Bottom Layer w0.2: U6.15@46.609,48.666 46.609,50.8 44.323,53.086 44.323,67.183 47.616,70.476 R33.1@48.641,70.476
LED34: R34.1 U6.1 | length 18.1
  Bottom Layer w0.2: U6.1@45.339,54.204 45.339,56.896 44.958,57.277 44.958,66.802 45.711,67.555 R34.1@50.038,67.555
LED35: R35.1 U6.2 | length 20.3
  Bottom Layer w0.2: U6.2@46.609,54.204 46.609,60.452 52.197,66.04 52.197,70.988 51.946,71.238 R35.1@51.054,71.238
LED36: R36.1 U6.3 | length 12.9
  Bottom Layer w0.2: U6.3@47.879,54.204 47.879,59.309 49.657,61.087 53.467,61.087 53.966,60.588 R36.1@53.966,59.817
LED37: R37.1 U6.4 | length 13.6
  Bottom Layer w0.2: U6.4@49.149,54.204 49.149,56.388 50.927,58.166 53.721,58.166 56.887,61.332 R37.1@56.887,62.992
LED38: R38.1 U6.5 | length 16
  Bottom Layer w0.2: U6.5@50.419,54.204 50.419,56.388 51.816,57.785 53.975,57.785 57.649,61.459 R38.1@57.649,65.913
LED39: R39.1 U6.6 | length 18.7
  Bottom Layer w0.2: U6.6@51.689,54.204 51.689,56.134 52.959,57.404 54.102,57.404 59.681,62.983 R39.1@59.681,68.961
LED40: R40.1 U6.7 | length 22.4
  Bottom Layer w0.2: U6.7@52.959,54.204 52.959,56.642 53.34,57.023 54.483,57.023 60.579,63.119 60.579,69.215 62.348,70.984 R40.1@62.348,72.009
LED41: R41.1 U7.15 | length 12
  Bottom Layer w0.2: R41.1@64.761,74.676 64.761,72.272 70.231,66.802 U7.15@70.231,64.922
LED42: R42.1 U7.1 | length 5.7
  Bottom Layer w0.2: R42.1@67.437,75.066 67.437,71.12 68.097,70.46 U7.1@68.961,70.46
LED43: R43.1 U7.2 | length 4.2
  Bottom Layer w0.2: R43.1@69.469,74.304 69.469,73.406 70.231,72.644 U7.2@70.231,70.46
LED44: R44.1 U7.3 | length 6
  Bottom Layer w0.2: U7.3@71.501,70.46 71.501,73.914 72.399,74.812 R44.1@73.66,74.812
LED45: R45.1 U7.4 | length 7.9
  Bottom Layer w0.2: U7.4@72.771,70.46 72.771,72.263 74.939,74.431 R45.1@77.978,74.431
LED46: R46.1 U7.5 | length 11
  Bottom Layer w0.2: U7.5@74.041,70.46 74.041,72.39 75.057,73.406 81.28,73.406 81.543,73.669 R46.1@81.543,74.676
LED47: R47.1 U7.6 | length 14.2
  Bottom Layer w0.2: U7.6@75.311,70.46 75.311,72.39 75.819,72.898 83.439,72.898 85.208,71.129 R47.1@86.614,71.129
LED48: R48.1 U7.7 | length 15.8
  Bottom Layer w0.2: U7.7@76.581,70.46 76.581,72.009 77.089,72.517 82.55,72.517 87.24,67.827 R48.1@88.646,67.827
LED49: R49.1 U8.15 | length 16.2
  Bottom Layer w0.2: U8.15@75.971,58.166 77.978,58.166 85.471,65.659 R49.1@89.036,65.659
LED50: R50.1 U8.1 | length 10.3
  Bottom Layer w0.2: U8.1@81.509,59.436 81.509,60.808 84.836,64.135 R50.1@89.036,64.135
LED51: R51.1 U8.2 | length 8.9
  Bottom Layer w0.2: U8.2@81.509,58.166 83.693,58.166 87.122,61.595 R51.1@89.036,61.595
LED52: R52.1 U8.3 | length 8.8
  Bottom Layer w0.2: U8.3@81.509,56.896 83.693,56.896 86.741,59.944 R52.1@89.036,59.944
LED53: R53.1 U8.4 | length 8.1
  Bottom Layer w0.2: U8.4@81.509,55.626 83.693,55.626 85.09,57.023 R53.1@89.036,57.023
LED54: R54.1 U8.5 | length 7.6
  Bottom Layer w0.2: U8.5@81.509,54.356 84.963,54.356 85.217,54.102 R54.1@89.036,54.102
LED55: R55.1 U8.6 | length 7.8
  Bottom Layer w0.2: U8.6@81.509,53.086 86.995,53.086 87.639,52.442 R55.1@87.639,51.054
LED56: R56.1 U8.7 | length 7.3
  Bottom Layer w0.2: U8.7@81.509,51.816 84.455,51.816 85.734,50.537 R56.1@85.734,48.006
LED57: R57.1 U9.15 | length 24.1
  Bottom Layer w0.2: U9.15@59.588,41.402 61.976,41.402 65.532,44.958 R57.1@82.178,44.958
LED58: R58.1 U9.1 | length 15.5
  Bottom Layer w0.2: U9.1@65.126,42.672 67.818,42.672 68.453,42.037 R58.1@80.4,42.037
LED59: R59.1 U9.2 | length 13.3
  Bottom Layer w0.2: U9.2@65.126,41.402 69.342,41.402 71.628,39.116 R59.1@77.479,39.116
LED60: R60.1 U9.3 | length 11.6
  Bottom Layer w0.2: U9.3@65.126,40.132 69.215,40.132 73.279,36.068 R60.1@75.066,36.068
LED61: R61.1 U9.4 | length 10.6
  Bottom Layer w0.2: U9.4@65.126,38.862 68.199,38.862 72.526,34.535 R61.1@72.526,33.147
LED62: R62.1 U9.5 | length 11.1
  Bottom Layer w0.2: U9.5@65.126,37.592 67.945,37.592 69.859,35.678 R62.1@69.859,30.099
LED63: R63.1 U9.6 | length 10.9
  Bottom Layer w0.2: U9.6@65.126,36.322 66.509,36.322 67.192,35.639 R63.1@67.192,27.051
LED64: R64.1 U9.7 | length 13.6
  Bottom Layer w0.2: R64.1@64.271,24.13 64.271,29.074 62.738,30.607 62.738,34.417 63.373,35.052 U9.7@65.126,35.052
LED65: R65.1 U10.15 | length 3.4
  Bottom Layer w0.2: U10.15@58.522,20.574 60.198,20.574 60.706,21.082 R65.1@61.731,21.082
LED66: R66.1 U10.1 | length 6.6
  Bottom Layer w0.2: U10.1@52.984,19.304 52.984,18.644 53.594,18.034 R66.1@58.683,18.034
LED67: R67.1 U10.2 | length 9.5
  Bottom Layer w0.2: U10.2@52.984,20.574 51.689,20.574 51.467,20.352 51.467,18.891 55.372,14.986 R67.1@56.27,14.986
LED68: R68.1 U10.3 | length 12.4
  Bottom Layer w0.2: U10.3@52.476,21.844 51.181,21.844 50.805,21.468 50.805,18.537 53.603,15.739 R68.1@53.603,12.065
LED69: R69.1 U10.4 | length 23.6
  Bottom Layer w0.2: U10.4@52.476,23.114 50.866,23.114 50.485,22.733 50.485,18.349 52.197,16.637 52.197,11.303 53.213,10.287 59.563,10.287 60.189,9.661 R69.1@60.189,9.017
LED70: R70.1 U10.5 | length 25.3
  Bottom Layer w0.2: U10.5@52.476,24.384 50.546,24.384 50.231,24.069 50.231,22.932 50.165,22.866 50.165,18.161 51.689,16.637 51.689,9.525 53.721,7.493 56.642,7.493 57.522,6.613 R70.1@57.522,5.969
NetBUZZER2_2: BUZZER2.2 Q15.3 R76.1 | length 12.5
  Bottom Layer w0.3: BUZZER2.2@83.312,19.812 80.629,22.495 R76.1@80.629,28.194 Q15.3@83.601,28.194
NetD1_2: D1.2 SW2.2 | length 2.8
  Bottom Layer w0.5: SW2.2@20.066,18.669 D1.2@22.827,18.669
NetLED1_2: LED1.2 R1.2 | length 1.9
  Top Layer w0.2: LED1.2@50.851,3 v1(51.641,3)
  Bottom Layer w0.2: v1(51.641,3) 52.666,3 R1.2@52.714,3.048
NetLED2_2: LED2.2 R2.2 | length 2
  Top Layer w0.2: LED2.2@48.151,6 v1@49.056,6
  Bottom Layer w0.2: v1(49.057,5.999) 50.143,5.999 R2.2@50.165,5.978
NetLED3_2: LED3.2 R3.2 | length 2
  Top Layer w0.2: LED3.2@45.351,9 46.211,9 v1(46.228,9.017)
  Bottom Layer w0.2: v1(46.228,9.017) R3.2@47.38,9.017
NetLED4_2: LED4.2 R4.2 | length 2.6
  Top Layer w0.2: LED4.2@42.651,12 v1(43.877,12)
  Bottom Layer w0.2: v1(43.877,12) 45.156,12 R4.2@45.221,12.065
NetLED5_2: LED5.2 R5.2 | length 2.5
  Top Layer w0.2: LED5.2@40.051,15 40.065,14.986 v1(41.402,14.986)
  Bottom Layer w0.2: v1(41.402,14.986) R5.2@42.554,14.986
NetLED6_2: LED6.2 R6.2 | length 2.7
  Top Layer w0.2: LED6.2@37.451,18 38.701,18 v1(38.735,18.034)
  Bottom Layer w0.2: v1(38.735,18.034) R6.2@40.141,18.034
NetLED7_2: LED7.2 R7.2 | length 2.6
  Top Layer w0.2: LED7.2@34.651,21 34.696,20.955 v1(36.195,20.955)
  Bottom Layer w0.2: v1(36.195,20.955) R7.2@37.22,20.955
NetLED8_2: LED8.2 R8.2 | length 3.8
  Top Layer w0.2: LED8.2@31.851,24 31.854,24.003 v1(34.036,24.003)
  Bottom Layer w0.2: v1(34.036,24.003) R8.2@35.623,24.003
NetLED9_2: LED9.2 R9.2 | length 2.4
  Top Layer w0.2: LED9.2@29.151,27 29.202,27.051 v1(30.48,27.051)
  Bottom Layer w0.2: v1(30.48,27.051) R9.2@31.505,27.051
